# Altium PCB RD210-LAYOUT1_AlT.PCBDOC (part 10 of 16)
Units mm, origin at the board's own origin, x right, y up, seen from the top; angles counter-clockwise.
Board outline 330 x 300 mm, 6 copper layers (TOP, Mid-Layer 1, Mid-Layer 2, Mid-Layer 3, Mid-Layer 4, BOTTOM), stack 1.422 mm thick; 981 components, 463 nets, 2326 pads, 12534 vias.
Unrouted connection lines stored in the file: 6.
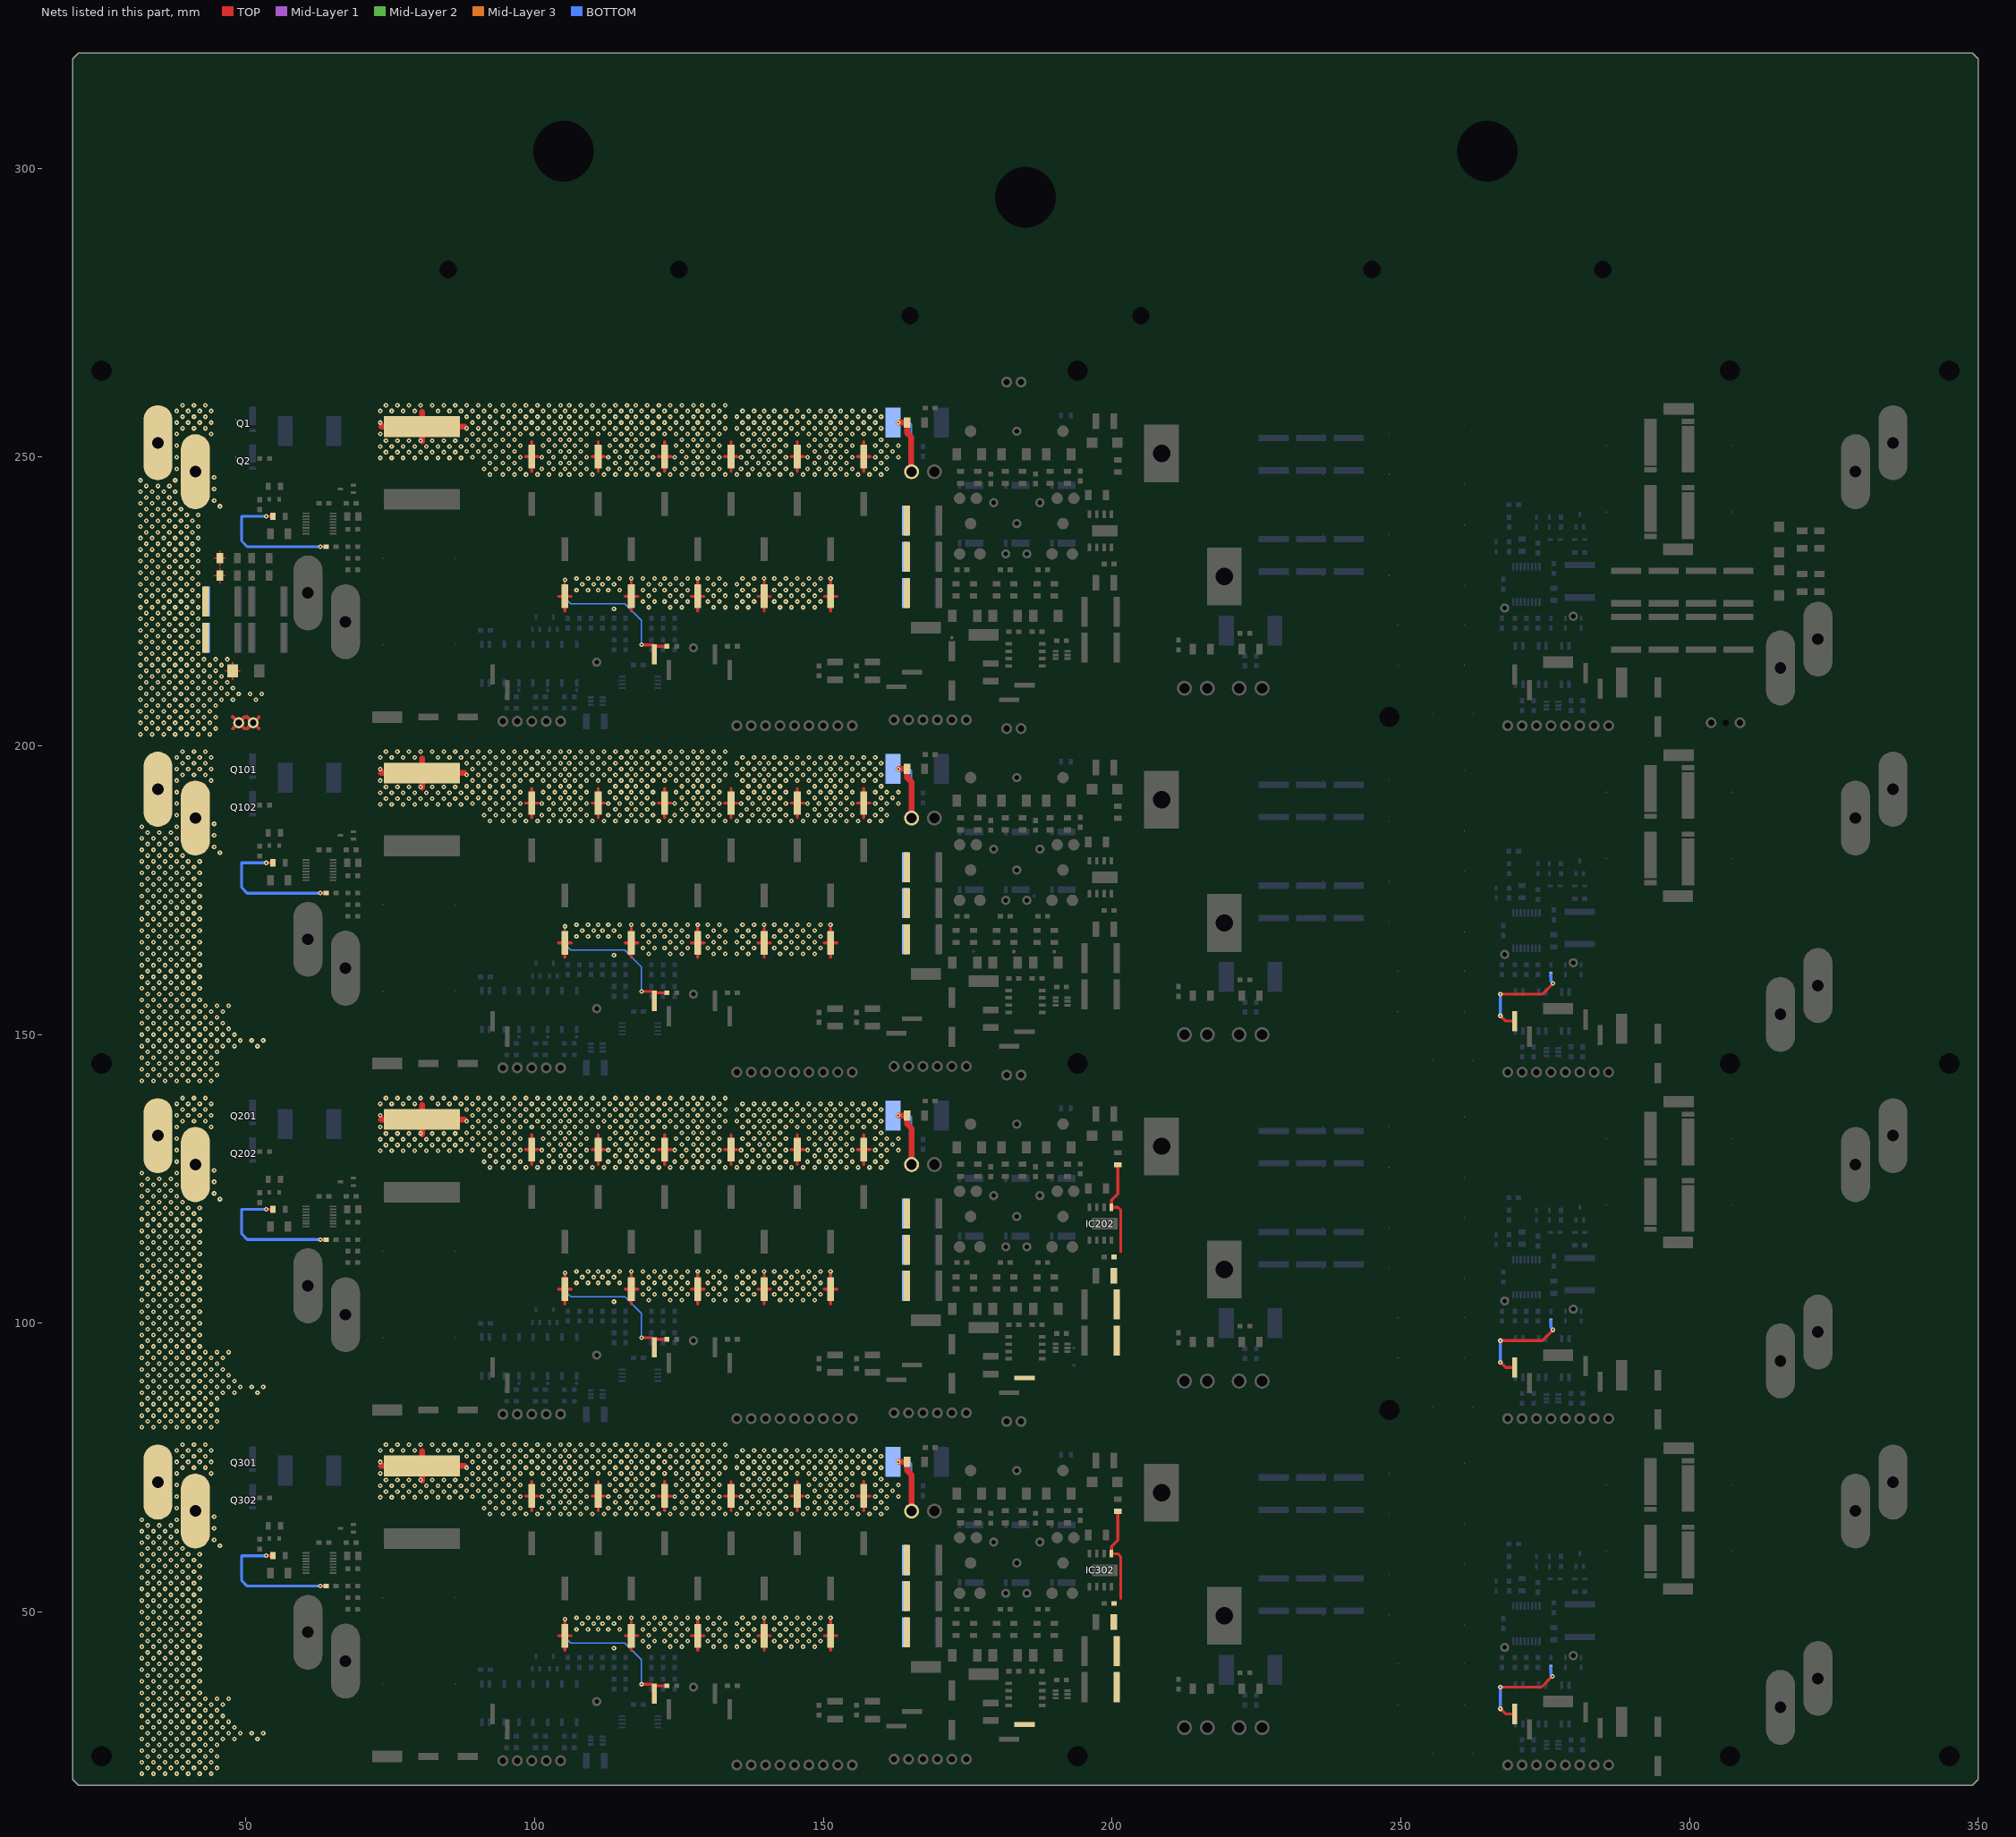
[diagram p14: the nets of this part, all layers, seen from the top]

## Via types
v1: diameter 0.8, hole 0.3, TOP to BOTTOM, 12534 vias

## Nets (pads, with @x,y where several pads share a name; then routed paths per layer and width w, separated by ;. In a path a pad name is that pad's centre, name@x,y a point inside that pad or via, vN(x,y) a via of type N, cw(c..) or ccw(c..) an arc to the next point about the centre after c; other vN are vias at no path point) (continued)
VP_12R0_SYS_I1_1: CN115.2 D111.1 | length 18.2
  TOP w0.5: v1(267.25,153.25) 268.15,152.35 CN115.2@269.73,152.35 ; v1(267.25,157) 274.5,157 v1(276.375,158.875)
  BOTTOM w0.5: v1(267.25,153.25) v1(267.25,157) ; D111.1@276,160.4 276,159.25 v1(276.375,158.875)
VP_12R0_SYS_I2_0: C235.2 C236.2 C237.1 C238.1 CN212.2 IC202.1 R209.1 | length 16.8
  TOP w0.5: R209.1@201,127.45 201,122.42 199.905,121.325 IC202.1@199.905,120.1 201,120.1 201.5,119.6 201.5,112.375
VP_12R0_SYS_I2_1: CN215.2 D211.1 | length 18.2
  TOP w0.5: v1(267.25,93.25) 268.15,92.35 CN215.2@269.73,92.35 ; v1(267.25,97) 274.5,97 v1(276.375,98.875)
  BOTTOM w0.5: v1(267.25,93.25) v1(267.25,97) ; D211.1@276,100.4 276,99.25 v1(276.375,98.875)
VP_12R0_SYS_I3_0: C335.2 C336.2 C337.1 C338.1 CN312.2 IC302.1 R309.1 | length 16.8
  TOP w0.5: R309.1@201,67.45 201,62.476 199.905,61.381 IC302.1@199.905,60.1 201,60.1 201.5,59.6 201.5,52.375
VP_12R0_SYS_I3_1: CN315.2 D311.1 | length 18
  TOP w0.5: v1(267.25,33.25) 268.15,32.35 CN315.2@269.73,32.35 ; v1(267.25,37) 274.375,37 v1(276.25,38.875)
  BOTTOM w0.5: v1(267.25,33.25) v1(267.25,37) ; D311.1@276,40.4 276,39.125 v1(276.25,38.875)
VP_H: C1.2 C3.2 C5.2 C7.2 C9.2 C11.2 CN6.1 CN6.2 D1.2 pad.@53.5,119.75 pad.@62.875,114.5 Q1.D Q2.D Q101.D Q102.D Q201.D Q202.D Q301.D Q302.D R1.2 R2.2 R101.2 R102.2 R201.2 R202.2 R301.2 R302.2 TN11.1 TN11.2 TN21.1 TN21.2 TN31.1 TN31.2 TN41.1 TN41.2 | length 159.9
  TOP w0.25: 44.525,229.5 C3.2@45.475,229.5 ; 44.525,232.5 C1.2@45.475,232.5 ; 45.475,228.225 C3.2@45.475,229.5 ; 45.475,230.775 C3.2@45.475,229.5 ; 45.475,231.225 C1.2@45.475,232.5 ; 45.475,233.775 C1.2@45.475,232.5 ; 46.425,213 D1.2@47.7,213 ; 46.425,229.5 C3.2@45.475,229.5 ; 46.425,232.5 C1.2@45.475,232.5 ; 47.7,211.525 D1.2@47.7,213 ; 47.7,214.475 D1.2@47.7,213 ; 48.975,213 D1.2@47.7,213
  TOP w0.5: 47.725,202.975 CN6.2@48.75,204 ; 47.725,205.025 CN6.2@48.75,204 ; 49.775,202.975 CN6.2@48.75,204 ; 49.775,205.025 CN6.2@48.75,204 ; 50.225,202.975 CN6.1@51.25,204 ; 50.225,205.025 CN6.1@51.25,204 ; 52.275,202.975 CN6.1@51.25,204 ; 52.275,205.025 CN6.1@51.25,204 ; v1(53.5,59.75) R301.2@54.7,59.75 ; v1(53.5,119.75) R201.2@54.7,119.75 ; v1(53.5,179.75) R101.2@54.7,179.75 ; v1(53.5,239.75) R1.2@54.7,239.75 ; v1(62.875,54.5) R302.2@63.9,54.5 ; v1(62.875,114.5) R202.2@63.9,114.5 ; v1(62.875,174.5) R102.2@63.9,174.5 ; v1(62.875,234.5) R2.2@63.9,234.5
  Mid-Layer 1 w0.5: 47.725,202.975 CN6.2@48.75,204 ; 47.725,205.025 CN6.2@48.75,204 ; 49.775,202.975 CN6.2@48.75,204 ; 49.775,205.025 CN6.2@48.75,204 ; 50.225,202.975 CN6.1@51.25,204 ; 50.225,205.025 CN6.1@51.25,204 ; 52.275,202.975 CN6.1@51.25,204 ; 52.275,205.025 CN6.1@51.25,204
  Mid-Layer 2 w0.5: 47.725,202.975 CN6.2@48.75,204 ; 47.725,205.025 CN6.2@48.75,204 ; 49.775,202.975 CN6.2@48.75,204 ; 49.775,205.025 CN6.2@48.75,204 ; 50.225,202.975 CN6.1@51.25,204 ; 50.225,205.025 CN6.1@51.25,204 ; 52.275,202.975 CN6.1@51.25,204 ; 52.275,205.025 CN6.1@51.25,204
  Mid-Layer 3 w0.5: 47.725,202.975 CN6.2@48.75,204 ; 47.725,205.025 CN6.2@48.75,204 ; 49.775,202.975 CN6.2@48.75,204 ; 49.775,205.025 CN6.2@48.75,204 ; 50.225,202.975 CN6.1@51.25,204 ; 50.225,205.025 CN6.1@51.25,204 ; 52.275,202.975 CN6.1@51.25,204 ; 52.275,205.025 CN6.1@51.25,204
  BOTTOM w0.5: v1(53.5,59.75) 49.25,59.75 49.25,55.5 50.25,54.5 v1(62.875,54.5) ; v1(53.5,119.75) 49.25,119.75 49.25,115.5 50.25,114.5 v1(62.875,114.5) ; v1(53.5,179.75) 49.25,179.75 49.25,175.5 50.25,174.5 v1(62.875,174.5) ; v1(53.5,239.75) 49.25,239.75 49.25,235.5 50.25,234.5 v1(62.875,234.5)
  other v1: 32,22 34,22 36,22 38,22 40,22 42,22 44,22 33,23 35,23 37,23 39,23 41,23 43,23 45,23 32,24 34,24 36,24 38,24 40,24 42,24 44,24 33,25 35,25 37,25 39,25 41,25 43,25 45,25 32,26 34,26 36,26 38,26 40,26 42,26 44,26 33,27 35,27 37,27 39,27 41,27 43,27 45,27 32,28 34,28 36,28 38,28 40,28 42,28 44,28 46,28 48,28 52,28 33,29 35,29 37,29 39,29 41,29 43,29 45,29 47,29 49,29 51,29 53,29 32,30 34,30 36,30 38,30 40,30 42,30 44,30 46,30 48,30 33,31 35,31 37,31 39,31 41,31 43,31 45,31 47,31 32,32 34,32 36,32 38,32 40,32 42,32 44,32 46,32 33,33 35,33 37,33 39,33 41,33 43,33 45,33 32,34 34,34 36,34 38,34 40,34 42,34 44,34 46,34 33,35 35,35 37,35 39,35 41,35 43,35 45,35 47,35 32,36 34,36 36,36 38,36 40,36 42,36 33,37 35,37 37,37 39,37 41,37 32,38 34,38 36,38 38,38 40,38 42,38 33,39 35,39 37,39 39,39 41,39 32,40 34,40 36,40 38,40 40,40 42,40 33,41 35,41 37,41 39,41 41,41 32,42 34,42 36,42 38,42 40,42 42,42 33,43 35,43 37,43 39,43 41,43 32,44 34,44 36,44 38,44 40,44 42,44 33,45 35,45 37,45 39,45 41,45 32,46 34,46 36,46 38,46 40,46 42,46 33,47 35,47 37,47 39,47 41,47 32,48 34,48 36,48 38,48 40,48 42,48 33,49 35,49 37,49 39,49 41,49 32,50 34,50 36,50 38,50 40,50 42,50 33,51 35,51 37,51 39,51 41,51 32,52 34,52 36,52 38,52 40,52 42,52 33,53 35,53 37,53 39,53 41,53 32,54 34,54 36,54 38,54 40,54 42,54 33,55 35,55 37,55 39,55 41,55 32,56 34,56 36,56 38,56 40,56 42,56 33,57 35,57 37,57 39,57 41,57 32,58 34,58 36,58 38,58 40,58 42,58 33,59 35,59 37,59 39,59 41,59 32,60 34,60 36,60 38,60 40,60 42,60 33,61 35,61 37,61 39,61 45.5,61.5 32,62 34,62 36,62 38,62 44.5,62.5 33,63 35,63 37,63 32,64 34,64 36,64 38,64 44.5,64.5 33,65 35,65 37,65 32,66 38,66 44.5,66.5 38,68 38,70 38,72 38,74 44,74 39,75 41,75 43,75 38,76 40,76 42,76 44,76 39,77 41,77 43,77 38,78 40,78 42,78 44,78 39,79 41,79 43,79 32,82 34,82 36,82 38,82 40,82 42,82 44,82 33,83 35,83 37,83 39,83 41,83 43,83 45,83 32,84 34,84 36,84 38,84 40,84 42,84 44,84 33,85 35,85 37,85 39,85 41,85 43,85 45,85 32,86 34,86 36,86 38,86 40,86 42,86 44,86 33,87 35,87 37,87 39,87 41,87 43,87 45,87 32,88 34,88 36,88 38,88 40,88 42,88 44,88 46,88 48,88 52,88 33,89 35,89 37,89 39,89 41,89 43,89 45,89 47,89 49,89 51,89 53,89 32,90 34,90 36,90 38,90 40,90 42,90 44,90 46,90 48,90 33,91 35,91 37,91 39,91 41,91 43,91 45,91 47,91 32,92 34,92 36,92 38,92 40,92 42,92 44,92 46,92 33,93 35,93 37,93 39,93 41,93 43,93 45,93 32,94 34,94 36,94 38,94 40,94 42,94 44,94 46,94 33,95 35,95 37,95 39,95 41,95 43,95 45,95 47,95 32,96 34,96 36,96 38,96 40,96 42,96 33,97 35,97 37,97 39,97 41,97 32,98 34,98 36,98 38,98 40,98 42,98 33,99 35,99 37,99 39,99 41,99 32,100 34,100 36,100 38,100 40,100 42,100 33,101 35,101 37,101 39,101 41,101 32,102 34,102 36,102 38,102 40,102 42,102 33,103 35,103 37,103 39,103 41,103 32,104 34,104 36,104 38,104 40,104 42,104 33,105 35,105 37,105 39,105 41,105 32,106 34,106 36,106 38,106 40,106 42,106 33,107 35,107 37,107 39,107 41,107 32,108 34,108 36,108 38,108 40,108 42,108 33,109 35,109 37,109 39,109 41,109 32,110 34,110 36,110 38,110 40,110 42,110 33,111 35,111 37,111 39,111 41,111 32,112 34,112 36,112 38,112 40,112 42,112 33,113 35,113 37,113 39,113 41,113 32,114 34,114 36,114 38,114 40,114 42,114 33,115 35,115 37,115 39,115 41,115 32,116 34,116 36,116 38,116 40,116 42,116 33,117 35,117 37,117 39,117 41,117 32,118 34,118 36,118 38,118 40,118 42,118 33,119 35,119 37,119 39,119 41,119 32,120 34,120 36,120 38,120 40,120 42,120 33,121 35,121 37,121 39,121 45.5,121.5 32,122 34,122 36,122 38,122 44.5,122.5 33,123 35,123 37,123 32,124 34,124 36,124 38,124 44.5,124.5 33,125 35,125 37,125 32,126 38,126 44.5,126.5 38,128 38,130 38,132 38,134 44,134 39,135 41,135 43,135 38,136 40,136 42,136 44,136 39,137 41,137 43,137 38,138 40,138 42,138 44,138 39,139 41,139 43,139 32,142 34,142 36,142 38,142 40,142 42,142 44,142 33,143 35,143 37,143 39,143 41,143 43,143 45,143 32,144 34,144 36,144 38,144 40,144 42,144 44,144 33,145 35,145 37,145 39,145 41,145 43,145 45,145 32,146 34,146 36,146 38,146 40,146 42,146 44,146 33,147 35,147 37,147 39,147 41,147 43,147 45,147 32,148 34,148 36,148 38,148 40,148 42,148 44,148 46,148 48,148 52,148 33,149 35,149 37,149 39,149 41,149 43,149 45,149 47,149 49,149 51,149 53,149 32,150 34,150 36,150 38,150 40,150 42,150 44,150 46,150 48,150 33,151 35,151 37,151 39,151 41,151 43,151 45,151 47,151 32,152 34,152 36,152 38,152 40,152 42,152 44,152 46,152 33,153 35,153 37,153 39,153 41,153 43,153 45,153 32,154 34,154 36,154 38,154 40,154 42,154 44,154 46,154 33,155 35,155 37,155 39,155 41,155 43,155 45,155 47,155 32,156 34,156 36,156 38,156 40,156 42,156 33,157 35,157 37,157 39,157 41,157 32,158 34,158 36,158 38,158 40,158 42,158 33,159 35,159 37,159 39,159 41,159 32,160 34,160 36,160 38,160 40,160 42,160 33,161 35,161 37,161 39,161 41,161 32,162 34,162 36,162 38,162 40,162 42,162 33,163 35,163 37,163 39,163 41,163 32,164 34,164 36,164 38,164 40,164 42,164 33,165 35,165 37,165 39,165 41,165 32,166 34,166 36,166 38,166 40,166 42,166 33,167 35,167 37,167 39,167 41,167 32,168 34,168 36,168 38,168 40,168 42,168 33,169 35,169 37,169 39,169 41,169 32,170 34,170 36,170 38,170 40,170 42,170 33,171 35,171 37,171 39,171 41,171 32,172 34,172 36,172 38,172 40,172 42,172 33,173 35,173 37,173 39,173 41,173 32,174 34,174 36,174 38,174 40,174 42,174 33,175 35,175 37,175 39,175 41,175 32,176 34,176 36,176 38,176 40,176 42,176 33,177 35,177 37,177 39,177 41,177 32,178 34,178 36,178 38,178 40,178 42,178 33,179 35,179 37,179 39,179 41,179 32,180 34,180 36,180 38,180 40,180 42,180 33,181 35,181 37,181 39,181 45.5,181.5 32,182 34,182 36,182 38,182 44.5,182.5 33,183 35,183 37,183 32,184 34,184 36,184 38,184 44.5,184.5 33,185 35,185 37,185 32,186 38,186 44.5,186.5 38,188 38,190 38,192 38,194 44,194 39,195 41,195 43,195 38,196 40,196 42,196 44,196 39,197 41,197 43,197 38,198 40,198 42,198 44,198 39,199 41,199 43,199 31.75,202 33.75,202 35.75,202 37.75,202 39.75,202 41.75,202 43.75,202 32.75,203 34.75,203 36.75,203 38.75,203 40.75,203 42.75,203 44.75,203 31.75,204 33.75,204 35.75,204 37.75,204 39.75,204 41.75,204 43.75,204 32.75,205 34.75,205 36.75,205 38.75,205 40.75,205 42.75,205 44.75,205 31.75,206 33.75,206 35.75,206 37.75,206 39.75,206 41.75,206 43.75,206 32.75,207 34.75,207 36.75,207 38.75,207 40.75,207 42.75,207 44.75,207 31.75,208 33.75,208 35.75,208 37.75,208 39.75,208 41.75,208 43.75,208 45.75,208 47.75,208 51.75,208 32.75,209 34.75,209 36.75,209 38.75,209 40.75,209 42.75,209 44.75,209 46.75,209 48.75,209 50.75,209 52.75,209 31.75,210 33.75,210 35.75,210 37.75,210 39.75,210 41.75,210 43.75,210 45.75,210 47.75,210 32.75,211 34.75,211 36.75,211 38.75,211 40.75,211 42.75,211 44.75,211 46.75,211 31.75,212 33.75,212 35.75,212 37.75,212 39.75,212 41.75,212 43.75,212 45.75,212 32.75,213 34.75,213 36.75,213 38.75,213 40.75,213 42.75,213 44.75,213 31.75,214 33.75,214 35.75,214 37.75,214 39.75,214 41.75,214 43.75,214 45.75,214 32.75,215 34.75,215 36.75,215 38.75,215 40.75,215 42.75,215 44.75,215 46.75,215 31.75,216 33.75,216 35.75,216 37.75,216 39.75,216 41.75,216 32.75,217 34.75,217 36.75,217 38.75,217 40.75,217 31.75,218 33.75,218 35.75,218 37.75,218 39.75,218 41.75,218 32.75,219 34.75,219 36.75,219 38.75,219 40.75,219 31.75,220 33.75,220 35.75,220 37.75,220 39.75,220 41.75,220 32.75,221 34.75,221 36.75,221 38.75,221 40.75,221 31.75,222 33.75,222 35.75,222 37.75,222 39.75,222 41.75,222 32.75,223 34.75,223 36.75,223 38.75,223 40.75,223 31.75,224 33.75,224 35.75,224 37.75,224 39.75,224 41.75,224 32.75,225 34.75,225 36.75,225 38.75,225 40.75,225 31.75,226 33.75,226 35.75,226 37.75,226 39.75,226 41.75,226 32.75,227 34.75,227 36.75,227 38.75,227 40.75,227 31.75,228 33.75,228 35.75,228 37.75,228 39.75,228 41.75,228 32.75,229 34.75,229 36.75,229 38.75,229 40.75,229 31.75,230 33.75,230 35.75,230 37.75,230 39.75,230 41.75,230 32.75,231 34.75,231 36.75,231 38.75,231 40.75,231 31.75,232 33.75,232 35.75,232 37.75,232 39.75,232 41.75,232 32.75,233 34.75,233 36.75,233 38.75,233 40.75,233 31.75,234 33.75,234 35.75,234 37.75,234 39.75,234 41.75,234 32.75,235 34.75,235 36.75,235 38.75,235 40.75,235 31.75,236 33.75,236 35.75,236 37.75,236 39.75,236 41.75,236 32.75,237 34.75,237 36.75,237 38.75,237 40.75,237 31.75,238 33.75,238 35.75,238 37.75,238 39.75,238 41.75,238 32.75,239 34.75,239 36.75,239 38.75,239 40.75,239 31.75,240 33.75,240 35.75,240 37.75,240 39.75,240 41.75,240 32.75,241 34.75,241 36.75,241 38.75,241 45.5,241.5 31.75,242 33.75,242 35.75,242 37.75,242 44.5,242.5 32.75,243 34.75,243 36.75,243 31.75,244 33.75,244 35.75,244 37.75,244 44.5,244.5 32.75,245 34.75,245 36.75,245 31.75,246 37.75,246 44.5,246.5 38,248 38,250 38,252 38,254 44,254 39,255 41,255 43,255 38,256 40,256 42,256 44,256 39,257 41,257 43,257 38,258 40,258 42,258 44,258 39,259 41,259 43,259
VP_H_0-1: C18.1 C19.1 C20.1 C21.1 C22.1 C23.1 C24.1 C25.1 C26.1 C27.1 C28.1 C29.2 C30.2 C31.2 C32.2 C33.2 C34.2 C43.1 C401.1 CN8.1 CN19.1 L1.2 R29.1 R47.2 | length 144.8
  TOP w0.25: C28.1@105.25,225.9 v1(105.25,228.75)
  TOP w0.5: 98.4,250.1 C18.1@99.5,250.1 ; 99.5,247.55 C18.1@99.5,250.1 ; 99.5,252.65 C18.1@99.5,250.1 ; 100.6,250.1 C18.1@99.5,250.1 ; 104.15,225.9 C28.1@105.25,225.9 ; 105.25,223.35 C28.1@105.25,225.9 ; 106.35,225.9 C28.1@105.25,225.9 ; 109.9,250.1 C19.1@111,250.1 ; 111,247.55 C19.1@111,250.1 ; 111,252.65 C19.1@111,250.1 ; 112.1,250.1 C19.1@111,250.1 ; 115.65,225.9 C27.1@116.75,225.9 ; 116.75,223.35 C27.1@116.75,225.9 ; 116.75,228.45 C27.1@116.75,225.9 ; 117.85,225.9 C27.1@116.75,225.9 ; v1(118.5,217.52) 118.52,217.5 120.48,217.5 CN19.1@120.73,217.25 ; CN19.1@120.73,215.85 CN19.1@120.73,217.25 ; 121.4,250.1 C20.1@122.5,250.1 ; 122.5,247.55 C20.1@122.5,250.1 ; 122.5,252.65 C20.1@122.5,250.1 ; R47.2@122.9,217.25 CN19.1@120.73,217.25 ; 123.6,250.1 C20.1@122.5,250.1 ; 127.15,225.9 C26.1@128.25,225.9 ; 128.25,223.35 C26.1@128.25,225.9 ; 128.25,228.45 C26.1@128.25,225.9 ; 129.35,225.9 C26.1@128.25,225.9 ; 132.9,250.1 C21.1@134,250.1 ; 134,247.55 C21.1@134,250.1 ; 134,252.65 C21.1@134,250.1 ; 135.1,250.1 C21.1@134,250.1 ; 138.65,225.9 C25.1@139.75,225.9 ; 139.75,223.35 C25.1@139.75,225.9 ; 139.75,228.45 C25.1@139.75,225.9 ; 140.85,225.9 C25.1@139.75,225.9 ; 144.4,250.1 C22.1@145.5,250.1 ; 145.5,247.55 C22.1@145.5,250.1 ; 145.5,252.65 C22.1@145.5,250.1 ; 146.6,250.1 C22.1@145.5,250.1 ; 150.15,225.9 C24.1@151.25,225.9 ; 151.25,223.35 C24.1@151.25,225.9 ; 151.25,228.45 C24.1@151.25,225.9 ; 152.35,225.9 C24.1@151.25,225.9 ; 155.9,250.1 C23.1@157,250.1 ; 157,247.55 C23.1@157,250.1 ; 157,252.65 C23.1@157,250.1 ; 158.1,250.1 C23.1@157,250.1
  TOP w1: 73.425,255.3 L1.2@80.5,255.3 ; v1@80.5,252.75 L1.2@80.5,255.3 ; 80.5,257.85 L1.2@80.5,255.3 ; 87.85,255.3 L1.2@80.5,255.3 ; v1(163,256) C401.1@164.475,256 164.475,254.25 165.225,253.5 165.225,247.545 CN8.1@165.27,247.5
  BOTTOM w0.25: v1(105.25,228.75) 105.25,225.625 106.25,224.625 115.625,224.625 118.5,221.75 v1(118.5,217.52) ; v1(163,256) 165,256 165.25,255.75 C43.1@165.25,251.85
  other v1: 113.75,223.75 119.75,224 123.5,224 125.5,224 131,224 133,224 135,224 137,224 142.5,224 144.5,224 146.5,224 148.5,224 118.75,225 120.75,225 122.5,225 124.5,225 126.5,225 130,225 132,225 136,225 138,225 141.5,225 143.5,225 145.5,225 147.5,225 149.5,225 119.75,226 123.5,226 125.5,226 131,226 133,226 135,226 137,226 142.5,226 144.5,226 146.5,226 148.5,226 107.25,227 109.25,227 111,227 112.75,227 114.75,227 118.75,227 120.75,227 122.5,227 124.5,227 126.5,227 130,227 132,227 136,227 138,227 141.5,227 143.5,227 145.5,227 147.5,227 149.5,227 108.25,228 110.25,228 111.75,228 113.75,228 119.75,228 121.75,228 123.5,228 125.5,228 131,228 133,228 135,228 137,228 142.5,228 144.5,228 146.5,228 148.5,228 107.25,229 109.25,229 111,229 112.75,229 114.75,229 116.75,229 118.75,229 120.75,229 122.5,229 124.5,229 126.5,229 128.25,229 130,229 132,229 136,229 138,229 139.75,229 141.5,229 143.5,229 145.5,229 147.5,229 149.5,229 151.25,229 92.25,247 94.5,247 96.5,247 98.5,247 100.5,247 102.5,247 104.5,247 106,247 108,247 110,247 112,247 114,247 116,247 117.5,247 119.5,247 121.5,247 123.5,247 125.5,247 127.5,247 129,247 131,247 133,247 135,247 137,247 139,247 140.5,247 142.5,247 144.5,247 146.5,247 148.5,247 150.5,247 152,247 154,247 156,247 158,247 160,247 91.25,248 93.25,248 95.5,248 97.5,248 101.25,248 103.25,248 105.25,248 107,248 109,248 112.75,248 114.75,248 116.75,248 118.5,248 120.5,248 124.25,248 126.25,248 128.25,248 130,248 132,248 135.75,248 137.75,248 139.75,248 141.5,248 143.5,248 147.25,248 149.25,248 151.25,248 153,248 155,248 159,248 161,248 92.25,249 94.5,249 96.5,249 102.5,249 104.5,249 106,249 108,249 114,249 116,249 117.5,249 119.5,249 125.5,249 127.5,249 129,249 131,249 136.75,249 138.75,249 140.5,249 142.5,249 148.5,249 150.5,249 152,249 154,249 160,249 73.25,249.875 75.25,249.875 77.25,249.875 79.25,249.875 81.25,249.875 83.25,249.875 85.25,249.875 87.25,249.875 89.25,250 91.25,250 93.25,250 95.5,250 97.5,250 101.25,250 103.25,250 105.25,250 107,250 109,250 112.75,250 114.75,250 116.75,250 118.5,250 120.5,250 124.25,250 126.25,250 128.25,250 130,250 132,250 135.75,250 137.75,250 139.75,250 141.5,250 143.5,250 147.25,250 149.25,250 151.25,250 153,250 155,250 159,250 161,250 163,250 74.25,250.875 76.25,250.875 78.25,250.875 80.25,250.875 82.25,250.875 84.25,250.875 86.25,250.875 88.25,251 90.25,251 92.25,251 94.5,251 96.5,251 102.5,251 104.5,251 106,251 108,251 114,251 116,251 117.5,251 119.5,251 125.5,251 127.5,251 129,251 131,251 137,251 139,251 140.5,251 142.5,251 148.5,251 150.5,251 152,251 154,251 160,251 162,251 73.25,251.875 75.25,251.875 77.25,251.875 79.25,251.875 81.25,251.875 83.25,251.875 85.25,251.875 87.25,251.875 89.25,252 91.25,252 93.25,252 95.5,252 97.5,252 101.5,252 103.5,252 105.25,252 107,252 109,252 113,252 115,252 116.75,252 118.5,252 120.5,252 124.5,252 126.5,252 128.25,252 130,252 132,252 136,252 138,252 139.75,252 141.5,252 143.5,252 147.5,252 149.5,252 151.25,252 153,252 155,252 159,252 161,252 163,252 74.25,252.875 76.25,252.875 78.25,252.875 80.25,252.875 82.25,252.875 84.25,252.875 86.25,252.875 88.25,253 90.25,253 92.25,253 94.5,253 96.5,253 102.5,253 104.5,253 106,253 108,253 114,253 116,253 117.5,253 119.5,253 125.5,253 127.5,253 129,253 131,253 137,253 139,253 140.5,253 142.5,253 148.5,253 150.5,253 152,253 154,253 160,253 73.25,254 89.25,254 91.25,254 93.25,254 95.5,254 97.5,254 99.5,254 101.5,254 103.5,254 105.25,254 107,254 109,254 111,254 113,254 115,254 116.75,254 118.5,254 120.5,254 122.5,254 124.5,254 126.5,254 128.25,254 130,254 132,254 136,254 138,254 139.75,254 141.5,254 143.5,254 145.5,254 147.5,254 149.5,254 151.25,254 153,254 155,254 157,254 159,254 88.25,255 90.25,255 92.25,255 94.5,255 96.5,255 98.5,255 100.5,255 102.5,255 104.5,255 106,255 108,255 110,255 112,255 114,255 116,255 117.5,255 119.5,255 121.5,255 123.5,255 125.5,255 127.5,255 129,255 131,255 133,255 135,255 137,255 139,255 140.5,255 142.5,255 144.5,255 146.5,255 148.5,255 150.5,255 152,255 154,255 156,255 158,255 160,255 73.25,256 89.25,256 91.25,256 93.25,256 95.5,256 97.5,256 99.5,256 101.5,256 103.5,256 105.25,256 107,256 109,256 111,256 113,256 115,256 116.75,256 118.5,256 120.5,256 122.5,256 124.5,256 126.5,256 128.25,256 130,256 132,256 136,256 138,256 139.75,256 141.5,256 143.5,256 145.5,256 147.5,256 149.5,256 151.25,256 153,256 155,256 157,256 159,256 88.25,257 90.25,257 92.25,257 94.5,257 96.5,257 98.5,257 100.5,257 102.5,257 104.5,257 106,257 108,257 110,257 112,257 114,257 116,257 117.5,257 119.5,257 121.5,257 123.5,257 125.5,257 127.5,257 129,257 131,257 133,257 135,257 137,257 139,257 140.5,257 142.5,257 144.5,257 146.5,257 148.5,257 150.5,257 152,257 154,257 156,257 158,257 160,257 73.25,258 75.25,258 77.25,258 79.25,258 83.25,258 85.25,258 87.25,258 89.25,258 91.25,258 93.25,258 95.5,258 97.5,258 99.5,258 101.5,258 103.5,258 105.25,258 107,258 109,258 111,258 113,258 115,258 116.75,258 118.5,258 120.5,258 122.5,258 124.5,258 126.5,258 128.25,258 130,258 132,258 136,258 138,258 139.75,258 141.5,258 143.5,258 145.5,258 147.5,258 149.5,258 151.25,258 153,258 155,258 157,258 159,258 74.25,259 76.25,259 78.25,259 80.25,259 82.25,259 84.25,259 86.25,259 88.25,259 90.25,259 92.25,259 94.5,259 96.5,259 98.5,259 100.5,259 102.5,259 104.5,259 106,259 108,259 110,259 112,259 114,259 116,259 117.5,259 119.5,259 121.5,259 123.5,259 125.5,259 127.5,259 129,259 131,259 133,259
VP_H_0-2: C118.1 C119.1 C120.1 C121.1 C122.1 C123.1 C124.1 C125.1 C126.1 C127.1 C128.1 C129.2 C130.2 C131.2 C132.2 C133.2 C134.2 C143.1 C411.1 CN108.1 CN119.1 L101.2 R129.1 R147.2 | length 144.9
  TOP w0.25: C128.1@105.25,165.9 v1(105.25,168.75)
  TOP w0.5: 98.4,190.1 C118.1@99.5,190.1 ; 99.5,187.55 C118.1@99.5,190.1 ; 99.5,192.65 C118.1@99.5,190.1 ; 100.6,190.1 C118.1@99.5,190.1 ; 104.15,165.9 C128.1@105.25,165.9 ; 105.25,163.35 C128.1@105.25,165.9 ; 106.35,165.9 C128.1@105.25,165.9 ; 109.9,190.1 C119.1@111,190.1 ; 111,187.55 C119.1@111,190.1 ; 111,192.65 C119.1@111,190.1 ; 112.1,190.1 C119.1@111,190.1 ; 115.65,165.9 C127.1@116.75,165.9 ; 116.75,163.35 C127.1@116.75,165.9 ; 116.75,168.45 C127.1@116.75,165.9 ; 117.85,165.9 C127.1@116.75,165.9 ; v1(118.5,157.5) 120.25,157.5 CN119.1@120.73,157.02 ; CN119.1@120.73,155.85 CN119.1@120.73,157.02 ; 121.4,190.1 C120.1@122.5,190.1 ; 122.5,187.55 C120.1@122.5,190.1 ; 122.5,192.65 C120.1@122.5,190.1 ; R147.2@122.9,157.25 120.73,157.25 CN119.1@120.73,157.02 ; 123.6,190.1 C120.1@122.5,190.1 ; 127.15,165.9 C126.1@128.25,165.9 ; 128.25,163.35 C126.1@128.25,165.9 ; 128.25,168.45 C126.1@128.25,165.9 ; 129.35,165.9 C126.1@128.25,165.9 ; 132.9,190.1 C121.1@134,190.1 ; 134,187.55 C121.1@134,190.1 ; 134,192.65 C121.1@134,190.1 ; 135.1,190.1 C121.1@134,190.1 ; 138.65,165.9 C125.1@139.75,165.9 ; 139.75,163.35 C125.1@139.75,165.9 ; 139.75,168.45 C125.1@139.75,165.9 ; 140.85,165.9 C125.1@139.75,165.9 ; 144.4,190.1 C122.1@145.5,190.1 ; 145.5,187.55 C122.1@145.5,190.1 ; 145.5,192.65 C122.1@145.5,190.1 ; 146.6,190.1 C122.1@145.5,190.1 ; 150.15,165.9 C124.1@151.25,165.9 ; 151.25,163.35 C124.1@151.25,165.9 ; 151.25,168.45 C124.1@151.25,165.9 ; 152.35,165.9 C124.1@151.25,165.9 ; 155.9,190.1 C123.1@157,190.1 ; 157,187.55 C123.1@157,190.1 ; 157,192.65 C123.1@157,190.1 ; 158.1,190.1 C123.1@157,190.1
  TOP w1: 73.4,195.3 L101.2@80.5,195.3 ; v1@80.5,192.75 L101.2@80.5,195.3 ; 80.5,197.85 L101.2@80.5,195.3 ; 87.85,195.3 L101.2@80.5,195.3 ; v1(163,196) C411.1@164.475,196 164.5,195.975 164.5,194.5 165.27,193.73 CN108.1@165.27,187.5
  BOTTOM w0.25: v1(105.25,168.75) 105.25,165.625 106.25,164.625 115.625,164.625 118.5,161.75 v1(118.5,157.5) ; v1(163,196) 165,196 165.25,195.75 C143.1@165.25,191.85
  other v1: 113.75,163.75 119.75,164 123.5,164 125.5,164 131,164 133,164 135,164 137,164 142.5,164 144.5,164 146.5,164 148.5,164 118.75,165 120.75,165 122.5,165 124.5,165 126.5,165 130,165 132,165 136,165 138,165 141.5,165 143.5,165 145.5,165 147.5,165 149.5,165 119.75,166 123.5,166 125.5,166 131,166 133,166 135,166 137,166 142.5,166 144.5,166 146.5,166 148.5,166 107.25,167 109.25,167 111,167 112.75,167 114.75,167 118.75,167 120.75,167 122.5,167 124.5,167 126.5,167 130,167 132,167 136,167 138,167 141.5,167 143.5,167 145.5,167 147.5,167 149.5,167 108.25,168 110.25,168 111.75,168 113.75,168 119.75,168 121.75,168 123.5,168 125.5,168 131,168 133,168 135,168 137,168 142.5,168 144.5,168 146.5,168 148.5,168 107.25,169 109.25,169 111,169 112.75,169 114.75,169 116.75,169 118.75,169 120.75,169 122.5,169 124.5,169 126.5,169 128.25,169 130,169 132,169 136,169 138,169 139.75,169 141.5,169 143.5,169 145.5,169 147.5,169 149.5,169 151.25,169 92.25,187 94.5,187 96.5,187 98.5,187 100.5,187 102.5,187 104.5,187 106,187 108,187 110,187 112,187 114,187 116,187 117.5,187 119.5,187 121.5,187 123.5,187 125.5,187 127.5,187 129,187 131,187 133,187 135,187 137,187 139,187 140.5,187 142.5,187 144.5,187 146.5,187 148.5,187 150.5,187 152,187 154,187 156,187 158,187 160,187 91.25,188 93.25,188 95.5,188 97.5,188 101.25,188 103.25,188 105.25,188 107,188 109,188 112.75,188 114.75,188 116.75,188 118.5,188 120.5,188 124.25,188 126.25,188 128.25,188 130,188 132,188 135.75,188 137.75,188 139.75,188 141.5,188 143.5,188 147.25,188 149.25,188 151.25,188 153,188 155,188 159,188 161,188 92.25,189 94.5,189 96.5,189 102.5,189 104.5,189 106,189 108,189 114,189 116,189 117.5,189 119.5,189 125.5,189 127.5,189 129,189 131,189 136.75,189 138.75,189 140.5,189 142.5,189 148.5,189 150.5,189 152,189 154,189 160,189 73.25,189.875 75.25,189.875 77.25,189.875 79.25,189.875 81.25,189.875 83.25,189.875 85.25,189.875 87.25,189.875 89.25,190 91.25,190 93.25,190 95.5,190 97.5,190 101.25,190 103.25,190 105.25,190 107,190 109,190 112.75,190 114.75,190 116.75,190 118.5,190 120.5,190 124.25,190 126.25,190 128.25,190 130,190 132,190 135.75,190 137.75,190 139.75,190 141.5,190 143.5,190 147.25,190 149.25,190 151.25,190 153,190 155,190 159,190 161,190 163,190 74.25,190.875 76.25,190.875 78.25,190.875 80.25,190.875 82.25,190.875 84.25,190.875 86.25,190.875 88.25,191 90.25,191 92.25,191 94.5,191 96.5,191 102.5,191 104.5,191 106,191 108,191 114,191 116,191 117.5,191 119.5,191 125.5,191 127.5,191 129,191 131,191 137,191 139,191 140.5,191 142.5,191 148.5,191 150.5,191 152,191 154,191 160,191 162,191 73.25,191.875 75.25,191.875 77.25,191.875 79.25,191.875 81.25,191.875 83.25,191.875 85.25,191.875 87.25,191.875 89.25,192 91.25,192 93.25,192 95.5,192 97.5,192 101.5,192 103.5,192 105.25,192 107,192 109,192 113,192 115,192 116.75,192 118.5,192 120.5,192 124.5,192 126.5,192 128.25,192 130,192 132,192 136,192 138,192 139.75,192 141.5,192 143.5,192 147.5,192 149.5,192 151.25,192 153,192 155,192 159,192 161,192 163,192 74.25,192.875 76.25,192.875 78.25,192.875 80.25,192.875 82.25,192.875 84.25,192.875 86.25,192.875 88.25,193 90.25,193 92.25,193 94.5,193 96.5,193 102.5,193 104.5,193 106,193 108,193 114,193 116,193 117.5,193 119.5,193 125.5,193 127.5,193 129,193 131,193 137,193 139,193 140.5,193 142.5,193 148.5,193 150.5,193 152,193 154,193 160,193 73.25,194 89.25,194 91.25,194 93.25,194 95.5,194 97.5,194 99.5,194 101.5,194 103.5,194 105.25,194 107,194 109,194 111,194 113,194 115,194 116.75,194 118.5,194 120.5,194 122.5,194 124.5,194 126.5,194 128.25,194 130,194 132,194 136,194 138,194 139.75,194 141.5,194 143.5,194 145.5,194 147.5,194 149.5,194 151.25,194 153,194 155,194 157,194 159,194 88.25,195 90.25,195 92.25,195 94.5,195 96.5,195 98.5,195 100.5,195 102.5,195 104.5,195 106,195 108,195 110,195 112,195 114,195 116,195 117.5,195 119.5,195 121.5,195 123.5,195 125.5,195 127.5,195 129,195 131,195 133,195 135,195 137,195 139,195 140.5,195 142.5,195 144.5,195 146.5,195 148.5,195 150.5,195 152,195 154,195 156,195 158,195 160,195 73.25,196 89.25,196 91.25,196 93.25,196 95.5,196 97.5,196 99.5,196 101.5,196 103.5,196 105.25,196 107,196 109,196 111,196 113,196 115,196 116.75,196 118.5,196 120.5,196 122.5,196 124.5,196 126.5,196 128.25,196 130,196 132,196 136,196 138,196 139.75,196 141.5,196 143.5,196 145.5,196 147.5,196 149.5,196 151.25,196 153,196 155,196 157,196 159,196 88.25,197 90.25,197 92.25,197 94.5,197 96.5,197 98.5,197 100.5,197 102.5,197 104.5,197 106,197 108,197 110,197 112,197 114,197 116,197 117.5,197 119.5,197 121.5,197 123.5,197 125.5,197 127.5,197 129,197 131,197 133,197 135,197 137,197 139,197 140.5,197 142.5,197 144.5,197 146.5,197 148.5,197 150.5,197 152,197 154,197 156,197 158,197 160,197 73.25,198 75.25,198 77.25,198 79.25,198 83.25,198 85.25,198 87.25,198 89.25,198 91.25,198 93.25,198 95.5,198 97.5,198 99.5,198 101.5,198 103.5,198 105.25,198 107,198 109,198 111,198 113,198 115,198 116.75,198 118.5,198 120.5,198 122.5,198 124.5,198 126.5,198 128.25,198 130,198 132,198 136,198 138,198 139.75,198 141.5,198 143.5,198 145.5,198 147.5,198 149.5,198 151.25,198 153,198 155,198 157,198 159,198 74.25,199 76.25,199 78.25,199 80.25,199 82.25,199 84.25,199 86.25,199 88.25,199 90.25,199 92.25,199 94.5,199 96.5,199 98.5,199 100.5,199 102.5,199 104.5,199 106,199 108,199 110,199 112,199 114,199 116,199 117.5,199 119.5,199 121.5,199 123.5,199 125.5,199 127.5,199 129,199 131,199 133,199
VP_H_0-3: C218.1 C219.1 C220.1 C221.1 C222.1 C223.1 C224.1 C225.1 C226.1 C227.1 C228.1 C229.2 C230.2 C231.2 C232.2 C233.2 C234.2 C243.1 C421.1 CN208.1 CN219.1 L201.2 R229.1 R247.2 | length 144.6
  TOP w0.5: 98.4,130.1 C218.1@99.5,130.1 ; 99.5,127.55 C218.1@99.5,130.1 ; 99.5,132.65 C218.1@99.5,130.1 ; 100.6,130.1 C218.1@99.5,130.1 ; 104.15,105.9 C228.1@105.25,105.9 ; 105.25,103.35 C228.1@105.25,105.9 ; v1@105.25,108.45 C228.1@105.25,105.9 ; 106.35,105.9 C228.1@105.25,105.9 ; 109.9,130.1 C219.1@111,130.1 ; 111,127.55 C219.1@111,130.1 ; 111,132.65 C219.1@111,130.1 ; 112.1,130.1 C219.1@111,130.1 ; 115.65,105.9 C227.1@116.75,105.9 ; 116.75,103.35 C227.1@116.75,105.9 ; 116.75,108.45 C227.1@116.75,105.9 ; 117.85,105.9 C227.1@116.75,105.9 ; v1(118.5,97.5) 120.25,97.5 CN219.1@120.73,97.02 ; CN219.1@120.73,95.85 CN219.1@120.73,97.02 ; 121.4,130.1 C220.1@122.5,130.1 ; 122.5,127.55 C220.1@122.5,130.1 ; 122.5,132.65 C220.1@122.5,130.1 ; R247.2@122.9,97.25 120.73,97.25 CN219.1@120.73,97.02 ; 123.6,130.1 C220.1@122.5,130.1 ; 127.15,105.9 C226.1@128.25,105.9 ; 128.25,103.35 C226.1@128.25,105.9 ; 128.25,108.45 C226.1@128.25,105.9 ; 129.35,105.9 C226.1@128.25,105.9 ; 132.9,130.1 C221.1@134,130.1 ; 134,127.55 C221.1@134,130.1 ; 134,132.65 C221.1@134,130.1 ; 135.1,130.1 C221.1@134,130.1 ; 138.65,105.9 C225.1@139.75,105.9 ; 139.75,103.35 C225.1@139.75,105.9 ; 139.75,108.45 C225.1@139.75,105.9 ; 140.85,105.9 C225.1@139.75,105.9 ; 144.4,130.1 C222.1@145.5,130.1 ; 145.5,127.55 C222.1@145.5,130.1 ; 145.5,132.65 C222.1@145.5,130.1 ; 146.6,130.1 C222.1@145.5,130.1 ; 150.15,105.9 C224.1@151.25,105.9 ; 151.25,103.35 C224.1@151.25,105.9 ; 151.25,108.45 C224.1@151.25,105.9 ; 152.35,105.9 C224.1@151.25,105.9 ; 155.9,130.1 C223.1@157,130.1 ; 157,127.55 C223.1@157,130.1 ; 157,132.65 C223.1@157,130.1 ; 158.1,130.1 C223.1@157,130.1
  TOP w1: 73.4,135.3 L201.2@80.5,135.3 ; v1@80.5,132.75 L201.2@80.5,135.3 ; 80.5,137.85 L201.2@80.5,135.3 ; 87.85,135.3 L201.2@80.5,135.3 ; v1(163,136) C421.1@164.475,136 164.5,135.975 164.5,134.5 165.27,133.73 CN208.1@165.27,127.5
  BOTTOM w0.25: v1(105.25,108.75) 105.25,105.625 106.25,104.625 115.625,104.625 118.5,101.75 v1(118.5,97.5) ; v1(163,136) 165,136 165.25,135.75 C243.1@165.25,131.85
  other v1: 113.75,103.75 119.75,104 123.5,104 125.5,104 131,104 133,104 135,104 137,104 142.5,104 144.5,104 146.5,104 148.5,104 118.75,105 120.75,105 122.5,105 124.5,105 126.5,105 130,105 132,105 136,105 138,105 141.5,105 143.5,105 145.5,105 147.5,105 149.5,105 119.75,106 123.5,106 125.5,106 131,106 133,106 135,106 137,106 142.5,106 144.5,106 146.5,106 148.5,106 107.25,107 109.25,107 111,107 112.75,107 114.75,107 118.75,107 120.75,107 122.5,107 124.5,107 126.5,107 130,107 132,107 136,107 138,107 141.5,107 143.5,107 145.5,107 147.5,107 149.5,107 108.25,108 110.25,108 111.75,108 113.75,108 119.75,108 121.75,108 123.5,108 125.5,108 131,108 133,108 135,108 137,108 142.5,108 144.5,108 146.5,108 148.5,108 107.25,109 109.25,109 111,109 112.75,109 114.75,109 116.75,109 118.75,109 120.75,109 122.5,109 124.5,109 126.5,109 128.25,109 130,109 132,109 136,109 138,109 139.75,109 141.5,109 143.5,109 145.5,109 147.5,109 149.5,109 151.25,109 92.25,127 94.5,127 96.5,127 98.5,127 100.5,127 102.5,127 104.5,127 106,127 108,127 110,127 112,127 114,127 116,127 117.5,127 119.5,127 121.5,127 123.5,127 125.5,127 127.5,127 129,127 131,127 133,127 135,127 137,127 139,127 140.5,127 142.5,127 144.5,127 146.5,127 148.5,127 150.5,127 152,127 154,127 156,127 158,127 160,127 91.25,128 93.25,128 95.5,128 97.5,128 101.25,128 103.25,128 105.25,128 107,128 109,128 112.75,128 114.75,128 116.75,128 118.5,128 120.5,128 124.25,128 126.25,128 128.25,128 130,128 132,128 135.75,128 137.75,128 139.75,128 141.5,128 143.5,128 147.25,128 149.25,128 151.25,128 153,128 155,128 159,128 161,128 92.25,129 94.5,129 96.5,129 102.5,129 104.5,129 106,129 108,129 114,129 116,129 117.5,129 119.5,129 125.5,129 127.5,129 129,129 131,129 136.75,129 138.75,129 140.5,129 142.5,129 148.5,129 150.5,129 152,129 154,129 160,129 73.25,129.875 75.25,129.875 77.25,129.875 79.25,129.875 81.25,129.875 83.25,129.875 85.25,129.875 87.25,129.875 89.25,130 91.25,130 93.25,130 95.5,130 97.5,130 101.25,130 103.25,130 105.25,130 107,130 109,130 112.75,130 114.75,130 116.75,130 118.5,130 120.5,130 124.25,130 126.25,130 128.25,130 130,130 132,130 135.75,130 137.75,130 139.75,130 141.5,130 143.5,130 147.25,130 149.25,130 151.25,130 153,130 155,130 159,130 161,130 163,130 74.25,130.875 76.25,130.875 78.25,130.875 80.25,130.875 82.25,130.875 84.25,130.875 86.25,130.875 88.25,131 90.25,131 92.25,131 94.5,131 96.5,131 102.5,131 104.5,131 106,131 108,131 114,131 116,131 117.5,131 119.5,131 125.5,131 127.5,131 129,131 131,131 137,131 139,131 140.5,131 142.5,131 148.5,131 150.5,131 152,131 154,131 160,131 162,131 73.25,131.875 75.25,131.875 77.25,131.875 79.25,131.875 81.25,131.875 83.25,131.875 85.25,131.875 87.25,131.875 89.25,132 91.25,132 93.25,132 95.5,132 97.5,132 101.5,132 103.5,132 105.25,132 107,132 109,132 113,132 115,132 116.75,132 118.5,132 120.5,132 124.5,132 126.5,132 128.25,132 130,132 132,132 136,132 138,132 139.75,132 141.5,132 143.5,132 147.5,132 149.5,132 151.25,132 153,132 155,132 159,132 161,132 163,132 74.25,132.875 76.25,132.875 78.25,132.875 80.25,132.875 82.25,132.875 84.25,132.875 86.25,132.875 88.25,133 90.25,133 92.25,133 94.5,133 96.5,133 102.5,133 104.5,133 106,133 108,133 114,133 116,133 117.5,133 119.5,133 125.5,133 127.5,133 129,133 131,133 137,133 139,133 140.5,133 142.5,133 148.5,133 150.5,133 152,133 154,133 160,133 73.25,134 89.25,134 91.25,134 93.25,134 95.5,134 97.5,134 99.5,134 101.5,134 103.5,134 105.25,134 107,134 109,134 111,134 113,134 115,134 116.75,134 118.5,134 120.5,134 122.5,134 124.5,134 126.5,134 128.25,134 130,134 132,134 136,134 138,134 139.75,134 141.5,134 143.5,134 145.5,134 147.5,134 149.5,134 151.25,134 153,134 155,134 157,134 159,134 88.25,135 90.25,135 92.25,135 94.5,135 96.5,135 98.5,135 100.5,135 102.5,135 104.5,135 106,135 108,135 110,135 112,135 114,135 116,135 117.5,135 119.5,135 121.5,135 123.5,135 125.5,135 127.5,135 129,135 131,135 133,135 135,135 137,135 139,135 140.5,135 142.5,135 144.5,135 146.5,135 148.5,135 150.5,135 152,135 154,135 156,135 158,135 160,135 73.25,136 89.25,136 91.25,136 93.25,136 95.5,136 97.5,136 99.5,136 101.5,136 103.5,136 105.25,136 107,136 109,136 111,136 113,136 115,136 116.75,136 118.5,136 120.5,136 122.5,136 124.5,136 126.5,136 128.25,136 130,136 132,136 136,136 138,136 139.75,136 141.5,136 143.5,136 145.5,136 147.5,136 149.5,136 151.25,136 153,136 155,136 157,136 159,136 88.25,137 90.25,137 92.25,137 94.5,137 96.5,137 98.5,137 100.5,137 102.5,137 104.5,137 106,137 108,137 110,137 112,137 114,137 116,137 117.5,137 119.5,137 121.5,137 123.5,137 125.5,137 127.5,137 129,137 131,137 133,137 135,137 137,137 139,137 140.5,137 142.5,137 144.5,137 146.5,137 148.5,137 150.5,137 152,137 154,137 156,137 158,137 160,137 73.25,138 75.25,138 77.25,138 79.25,138 83.25,138 85.25,138 87.25,138 89.25,138 91.25,138 93.25,138 95.5,138 97.5,138 99.5,138 101.5,138 103.5,138 105.25,138 107,138 109,138 111,138 113,138 115,138 116.75,138 118.5,138 120.5,138 122.5,138 124.5,138 126.5,138 128.25,138 130,138 132,138 136,138 138,138 139.75,138 141.5,138 143.5,138 145.5,138 147.5,138 149.5,138 151.25,138 153,138 155,138 157,138 159,138 74.25,139 76.25,139 78.25,139 80.25,139 82.25,139 84.25,139 86.25,139 88.25,139 90.25,139 92.25,139 94.5,139 96.5,139 98.5,139 100.5,139 102.5,139 104.5,139 106,139 108,139 110,139 112,139 114,139 116,139 117.5,139 119.5,139 121.5,139 123.5,139 125.5,139 127.5,139 129,139 131,139 133,139
VP_H_0-4: C318.1 C319.1 C320.1 C321.1 C322.1 C323.1 C324.1 C325.1 C326.1 C327.1 C328.1 C329.2 C330.2 C331.2 C332.2 C333.2 C334.2 C343.1 C431.1 CN308.1 CN319.1 L301.2 R329.1 R347.2 | length 144.9
  TOP w0.5: 98.4,70.1 C318.1@99.5,70.1 ; 99.5,67.55 C318.1@99.5,70.1 ; 99.5,72.65 C318.1@99.5,70.1 ; 100.6,70.1 C318.1@99.5,70.1 ; 104.15,45.9 C328.1@105.25,45.9 ; 105.25,43.35 C328.1@105.25,45.9 ; v1(105.25,48.75) C328.1@105.25,45.9 ; 106.35,45.9 C328.1@105.25,45.9 ; 109.9,70.1 C319.1@111,70.1 ; 111,67.55 C319.1@111,70.1 ; 111,72.65 C319.1@111,70.1 ; 112.1,70.1 C319.1@111,70.1 ; 115.65,45.9 C327.1@116.75,45.9 ; 116.75,43.35 C327.1@116.75,45.9 ; 116.75,48.45 C327.1@116.75,45.9 ; 117.85,45.9 C327.1@116.75,45.9 ; v1(118.5,37.5) 120.25,37.5 CN319.1@120.73,37.02 ; CN319.1@120.73,35.85 CN319.1@120.73,37.02 ; 121.4,70.1 C320.1@122.5,70.1 ; 122.5,67.55 C320.1@122.5,70.1 ; 122.5,72.65 C320.1@122.5,70.1 ; R347.2@122.9,37.25 120.75,37.25 120.73,37.23 CN319.1@120.73,37.02 ; 123.6,70.1 C320.1@122.5,70.1 ; 127.15,45.9 C326.1@128.25,45.9 ; 128.25,43.35 C326.1@128.25,45.9 ; 128.25,48.45 C326.1@128.25,45.9 ; 129.35,45.9 C326.1@128.25,45.9 ; 132.9,70.1 C321.1@134,70.1 ; 134,67.55 C321.1@134,70.1 ; 134,72.65 C321.1@134,70.1 ; 135.1,70.1 C321.1@134,70.1 ; 138.65,45.9 C325.1@139.75,45.9 ; 139.75,43.35 C325.1@139.75,45.9 ; 139.75,48.45 C325.1@139.75,45.9 ; 140.85,45.9 C325.1@139.75,45.9 ; 144.4,70.1 C322.1@145.5,70.1 ; 145.5,67.55 C322.1@145.5,70.1 ; 145.5,72.65 C322.1@145.5,70.1 ; 146.6,70.1 C322.1@145.5,70.1 ; 150.15,45.9 C324.1@151.25,45.9 ; 151.25,43.35 C324.1@151.25,45.9 ; 151.25,48.45 C324.1@151.25,45.9 ; 152.35,45.9 C324.1@151.25,45.9 ; 155.9,70.1 C323.1@157,70.1 ; 157,67.55 C323.1@157,70.1 ; 157,72.65 C323.1@157,70.1 ; 158.1,70.1 C323.1@157,70.1
  TOP w1: 73.4,75.3 L301.2@80.5,75.3 ; v1@80.5,72.75 L301.2@80.5,75.3 ; 80.5,77.85 L301.2@80.5,75.3 ; 87.85,75.3 L301.2@80.5,75.3 ; v1(163,76) C431.1@164.475,76 164.5,75.975 164.5,74.5 165.27,73.73 CN308.1@165.27,67.5
  BOTTOM w0.25: v1(105.25,48.75) 105.25,45.625 106.25,44.625 115.625,44.625 118.5,41.75 v1(118.5,37.5) ; v1(163,76) 165,76 165.25,75.75 C343.1@165.25,71.85
  other v1: 113.75,43.75 119.75,44 123.5,44 125.5,44 131,44 133,44 135,44 137,44 142.5,44 144.5,44 146.5,44 148.5,44 118.75,45 120.75,45 122.5,45 124.5,45 126.5,45 130,45 132,45 136,45 138,45 141.5,45 143.5,45 145.5,45 147.5,45 149.5,45 119.75,46 123.5,46 125.5,46 131,46 133,46 135,46 137,46 142.5,46 144.5,46 146.5,46 148.5,46 107.25,47 109.25,47 111,47 112.75,47 114.75,47 118.75,47 120.75,47 122.5,47 124.5,47 126.5,47 130,47 132,47 136,47 138,47 141.5,47 143.5,47 145.5,47 147.5,47 149.5,47 108.25,48 110.25,48 111.75,48 113.75,48 119.75,48 121.75,48 123.5,48 125.5,48 131,48 133,48 135,48 137,48 142.5,48 144.5,48 146.5,48 148.5,48 107.25,49 109.25,49 111,49 112.75,49 114.75,49 116.75,49 118.75,49 120.75,49 122.5,49 124.5,49 126.5,49 128.25,49 130,49 132,49 136,49 138,49 139.75,49 141.5,49 143.5,49 145.5,49 147.5,49 149.5,49 151.25,49 92.25,67 94.5,67 96.5,67 98.5,67 100.5,67 102.5,67 104.5,67 106,67 108,67 110,67 112,67 114,67 116,67 117.5,67 119.5,67 121.5,67 123.5,67 125.5,67 127.5,67 129,67 131,67 133,67 135,67 137,67 139,67 140.5,67 142.5,67 144.5,67 146.5,67 148.5,67 150.5,67 152,67 154,67 156,67 158,67 160,67 91.25,68 93.25,68 95.5,68 97.5,68 101.25,68 103.25,68 105.25,68 107,68 109,68 112.75,68 114.75,68 116.75,68 118.5,68 120.5,68 124.25,68 126.25,68 128.25,68 130,68 132,68 135.75,68 137.75,68 139.75,68 141.5,68 143.5,68 147.25,68 149.25,68 151.25,68 153,68 155,68 159,68 161,68 92.25,69 94.5,69 96.5,69 102.5,69 104.5,69 106,69 108,69 114,69 116,69 117.5,69 119.5,69 125.5,69 127.5,69 129,69 131,69 136.75,69 138.75,69 140.5,69 142.5,69 148.5,69 150.5,69 152,69 154,69 160,69 73.25,69.875 75.25,69.875 77.25,69.875 79.25,69.875 81.25,69.875 83.25,69.875 85.25,69.875 87.25,69.875 89.25,70 91.25,70 93.25,70 95.5,70 97.5,70 101.25,70 103.25,70 105.25,70 107,70 109,70 112.75,70 114.75,70 116.75,70 118.5,70 120.5,70 124.25,70 126.25,70 128.25,70 130,70 132,70 135.75,70 137.75,70 139.75,70 141.5,70 143.5,70 147.25,70 149.25,70 151.25,70 153,70 155,70 159,70 161,70 163,70 74.25,70.875 76.25,70.875 78.25,70.875 80.25,70.875 82.25,70.875 84.25,70.875 86.25,70.875 88.25,71 90.25,71 92.25,71 94.5,71 96.5,71 102.5,71 104.5,71 106,71 108,71 114,71 116,71 117.5,71 119.5,71 125.5,71 127.5,71 129,71 131,71 137,71 139,71 140.5,71 142.5,71 148.5,71 150.5,71 152,71 154,71 160,71 162,71 73.25,71.875 75.25,71.875 77.25,71.875 79.25,71.875 81.25,71.875 83.25,71.875 85.25,71.875 87.25,71.875 89.25,72 91.25,72 93.25,72 95.5,72 97.5,72 101.5,72 103.5,72 105.25,72 107,72 109,72 113,72 115,72 116.75,72 118.5,72 120.5,72 124.5,72 126.5,72 128.25,72 130,72 132,72 136,72 138,72 139.75,72 141.5,72 143.5,72 147.5,72 149.5,72 151.25,72 153,72 155,72 159,72 161,72 163,72 74.25,72.875 76.25,72.875 78.25,72.875 80.25,72.875 82.25,72.875 84.25,72.875 86.25,72.875 88.25,73 90.25,73 92.25,73 94.5,73 96.5,73 102.5,73 104.5,73 106,73 108,73 114,73 116,73 117.5,73 119.5,73 125.5,73 127.5,73 129,73 131,73 137,73 139,73 140.5,73 142.5,73 148.5,73 150.5,73 152,73 154,73 160,73 73.25,74 89.25,74 91.25,74 93.25,74 95.5,74 97.5,74 99.5,74 101.5,74 103.5,74 105.25,74 107,74 109,74 111,74 113,74 115,74 116.75,74 118.5,74 120.5,74 122.5,74 124.5,74 126.5,74 128.25,74 130,74 132,74 136,74 138,74 139.75,74 141.5,74 143.5,74 145.5,74 147.5,74 149.5,74 151.25,74 153,74 155,74 157,74 159,74 88.25,75 90.25,75 92.25,75 94.5,75 96.5,75 98.5,75 100.5,75 102.5,75 104.5,75 106,75 108,75 110,75 112,75 114,75 116,75 117.5,75 119.5,75 121.5,75 123.5,75 125.5,75 127.5,75 129,75 131,75 133,75 135,75 137,75 139,75 140.5,75 142.5,75 144.5,75 146.5,75 148.5,75 150.5,75 152,75 154,75 156,75 158,75 160,75 73.25,76 89.25,76 91.25,76 93.25,76 95.5,76 97.5,76 99.5,76 101.5,76 103.5,76 105.25,76 107,76 109,76 111,76 113,76 115,76 116.75,76 118.5,76 120.5,76 122.5,76 124.5,76 126.5,76 128.25,76 130,76 132,76 136,76 138,76 139.75,76 141.5,76 143.5,76 145.5,76 147.5,76 149.5,76 151.25,76 153,76 155,76 157,76 159,76 88.25,77 90.25,77 92.25,77 94.5,77 96.5,77 98.5,77 100.5,77 102.5,77 104.5,77 106,77 108,77 110,77 112,77 114,77 116,77 117.5,77 119.5,77 121.5,77 123.5,77 125.5,77 127.5,77 129,77 131,77 133,77 135,77 137,77 139,77 140.5,77 142.5,77 144.5,77 146.5,77 148.5,77 150.5,77 152,77 154,77 156,77 158,77 160,77 73.25,78 75.25,78 77.25,78 79.25,78 83.25,78 85.25,78 87.25,78 89.25,78 91.25,78 93.25,78 95.5,78 97.5,78 99.5,78 101.5,78 103.5,78 105.25,78 107,78 109,78 111,78 113,78 115,78 116.75,78 118.5,78 120.5,78 122.5,78 124.5,78 126.5,78 128.25,78 130,78 132,78 136,78 138,78 139.75,78 141.5,78 143.5,78 145.5,78 147.5,78 149.5,78 151.25,78 153,78 155,78 157,78 159,78 74.25,79 76.25,79 78.25,79 80.25,79 82.25,79 84.25,79 86.25,79 88.25,79 90.25,79 92.25,79 94.5,79 96.5,79 98.5,79 100.5,79 102.5,79 104.5,79 106,79 108,79 110,79 112,79 114,79 116,79 117.5,79 119.5,79 121.5,79 123.5,79 125.5,79 127.5,79 129,79 131,79 133,79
